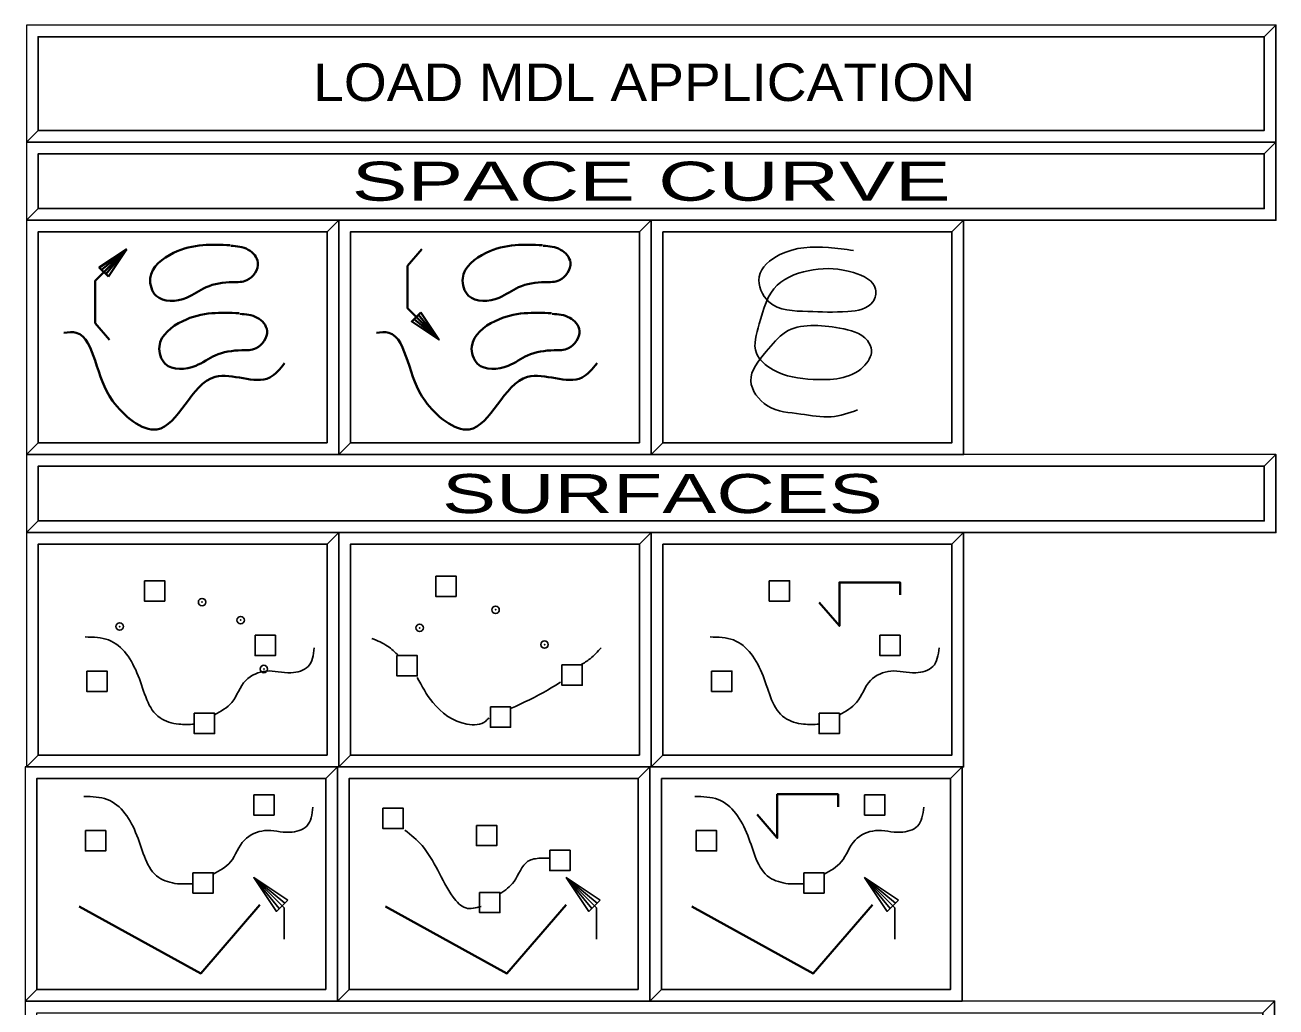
# Model space of a CAD drawing. Extents: x 95906.8 to 95923.6, y 90964.8 to 90972.8.
# Drawn here: x 95914.531 to 95916.132, y 90968.551 to 90969.808 of the extents above; entities that cross this region are included whole.
import ezdxf
from ezdxf.enums import TextEntityAlignment as Align

# ---------------------------------------------------------------- set-up
doc = ezdxf.new("R2010")
doc.units = 0
doc.header["$LTSCALE"] = 0.019
doc.header["$PDMODE"] = 32
doc.header["$PDSIZE"] = 0.0095
for name, color, linetype, lineweight in [('11', 7, 'Continuous', 25), ('17', 7, 'Continuous', 25), ('2', 7, 'Continuous', 13), ('3', 7, 'Continuous', 25), ('6', 7, 'Continuous', 25), ('7', 7, 'Continuous', 35)]:
    doc.layers.add(name, color=color, linetype=linetype, lineweight=lineweight)

msp = doc.modelspace()

# ---------------------------------------------------------------- linework, layer by layer
at = {"layer": '11'}
for points in [[(95914.5473, 90969.6733), (95916.1173, 90969.6733), (95916.1173, 90969.7933), (95914.5473, 90969.7933)], [(95914.5473, 90969.2733), (95914.9173, 90969.2733), (95914.9173, 90969.5433), (95914.5473, 90969.5433)], [(95914.9473, 90969.2733), (95915.3173, 90969.2733), (95915.3173, 90969.5433), (95914.9473, 90969.5433)], [(95915.3473, 90969.2733), (95915.7173, 90969.2733), (95915.7173, 90969.5433), (95915.3473, 90969.5433)], [(95914.5473, 90968.8733), (95914.9173, 90968.8733), (95914.9173, 90969.1433), (95914.5473, 90969.1433)], [(95914.9473, 90968.8733), (95915.3173, 90968.8733), (95915.3173, 90969.1433), (95914.9473, 90969.1433)], [(95915.3473, 90968.8733), (95915.7173, 90968.8733), (95915.7173, 90969.1433), (95915.3473, 90969.1433)], [(95914.5456, 90968.5733), (95914.9156, 90968.5733), (95914.9156, 90968.8433), (95914.5456, 90968.8433)], [(95914.9456, 90968.5733), (95915.3156, 90968.5733), (95915.3156, 90968.8433), (95914.9456, 90968.8433)], [(95915.3456, 90968.5733), (95915.7156, 90968.5733), (95915.7156, 90968.8433), (95915.3456, 90968.8433)]]:
    msp.add_lwpolyline(points, close=True, dxfattribs=at)
at = {"layer": '17'}
for points in [[(95914.5473, 90969.5733), (95916.1173, 90969.5733), (95916.1173, 90969.6433), (95914.5473, 90969.6433)], [(95914.5473, 90969.1733), (95916.1173, 90969.1733), (95916.1173, 90969.2433), (95914.5473, 90969.2433)]]:
    msp.add_lwpolyline(points, close=True, dxfattribs=at)
at = {"layer": '2'}
for points in [[(95914.5323, 90969.8083), (95914.5323, 90969.6583), (95914.5473, 90969.6733), (95914.5473, 90969.7933), (95916.1173, 90969.7933), (95916.1323, 90969.8083)], [(95914.5323, 90969.6583), (95914.5323, 90969.5583), (95914.5473, 90969.5733), (95914.5473, 90969.6433), (95916.1173, 90969.6433), (95916.1323, 90969.6583)], [(95914.5323, 90969.5583), (95914.5323, 90969.2583), (95914.5473, 90969.2733), (95914.5473, 90969.5433), (95914.9173, 90969.5433), (95914.9323, 90969.5583)], [(95914.9323, 90969.5583), (95914.9323, 90969.2583), (95914.9473, 90969.2733), (95914.9473, 90969.5433), (95915.3173, 90969.5433), (95915.3323, 90969.5583)], [(95915.3323, 90969.5583), (95915.3323, 90969.2583), (95915.3473, 90969.2733), (95915.3473, 90969.5433), (95915.7173, 90969.5433), (95915.7323, 90969.5583)], [(95914.5323, 90969.2583), (95914.5323, 90969.1583), (95914.5473, 90969.1733), (95914.5473, 90969.2433), (95916.1173, 90969.2433), (95916.1323, 90969.2583)], [(95914.5323, 90969.1583), (95914.5323, 90968.8583), (95914.5473, 90968.8733), (95914.5473, 90969.1433), (95914.9173, 90969.1433), (95914.9323, 90969.1583)], [(95914.9323, 90969.1583), (95914.9323, 90968.8583), (95914.9473, 90968.8733), (95914.9473, 90969.1433), (95915.3173, 90969.1433), (95915.3323, 90969.1583)], [(95915.3323, 90969.1583), (95915.3323, 90968.8583), (95915.3473, 90968.8733), (95915.3473, 90969.1433), (95915.7173, 90969.1433), (95915.7323, 90969.1583)], [(95914.5306, 90968.8583), (95914.5306, 90968.5583), (95914.5456, 90968.5733), (95914.5456, 90968.8433), (95914.9156, 90968.8433), (95914.9306, 90968.8583)], [(95914.9306, 90968.8583), (95914.9306, 90968.5583), (95914.9456, 90968.5733), (95914.9456, 90968.8433), (95915.3156, 90968.8433), (95915.3306, 90968.8583)], [(95915.3306, 90968.8583), (95915.3306, 90968.5583), (95915.3456, 90968.5733), (95915.3456, 90968.8433), (95915.7156, 90968.8433), (95915.7306, 90968.8583)], [(95914.5306, 90968.5583), (95914.5306, 90968.4583), (95914.5456, 90968.4733), (95914.5456, 90968.5433), (95916.1156, 90968.5433), (95916.1306, 90968.5583)]]:
    msp.add_lwpolyline(points, close=True, dxfattribs=at)
at = {"layer": '3'}
for points in [[(95914.5323, 90969.6583), (95916.1323, 90969.6583), (95916.1323, 90969.8083), (95916.1173, 90969.7933), (95916.1173, 90969.6733), (95914.5473, 90969.6733)], [(95914.5323, 90969.5583), (95916.1323, 90969.5583), (95916.1323, 90969.6583), (95916.1173, 90969.6433), (95916.1173, 90969.5733), (95914.5473, 90969.5733)], [(95914.5323, 90969.2583), (95914.9323, 90969.2583), (95914.9323, 90969.5583), (95914.9173, 90969.5433), (95914.9173, 90969.2733), (95914.5473, 90969.2733)], [(95914.9323, 90969.2583), (95915.3323, 90969.2583), (95915.3323, 90969.5583), (95915.3173, 90969.5433), (95915.3173, 90969.2733), (95914.9473, 90969.2733)], [(95915.3323, 90969.2583), (95915.7323, 90969.2583), (95915.7323, 90969.5583), (95915.7173, 90969.5433), (95915.7173, 90969.2733), (95915.3473, 90969.2733)], [(95914.5323, 90969.1583), (95916.1323, 90969.1583), (95916.1323, 90969.2583), (95916.1173, 90969.2433), (95916.1173, 90969.1733), (95914.5473, 90969.1733)], [(95914.5323, 90968.8583), (95914.9323, 90968.8583), (95914.9323, 90969.1583), (95914.9173, 90969.1433), (95914.9173, 90968.8733), (95914.5473, 90968.8733)], [(95914.9323, 90968.8583), (95915.3323, 90968.8583), (95915.3323, 90969.1583), (95915.3173, 90969.1433), (95915.3173, 90968.8733), (95914.9473, 90968.8733)], [(95915.3323, 90968.8583), (95915.7323, 90968.8583), (95915.7323, 90969.1583), (95915.7173, 90969.1433), (95915.7173, 90968.8733), (95915.3473, 90968.8733)], [(95914.5306, 90968.5583), (95914.9306, 90968.5583), (95914.9306, 90968.8583), (95914.9156, 90968.8433), (95914.9156, 90968.5733), (95914.5456, 90968.5733)], [(95914.9306, 90968.5583), (95915.3306, 90968.5583), (95915.3306, 90968.8583), (95915.3156, 90968.8433), (95915.3156, 90968.5733), (95914.9456, 90968.5733)], [(95915.3306, 90968.5583), (95915.7306, 90968.5583), (95915.7306, 90968.8583), (95915.7156, 90968.8433), (95915.7156, 90968.5733), (95915.3456, 90968.5733)], [(95914.5306, 90968.4583), (95916.1306, 90968.4583), (95916.1306, 90968.5583), (95916.1156, 90968.5433), (95916.1156, 90968.4733), (95914.5456, 90968.4733)]]:
    msp.add_lwpolyline(points, close=True, dxfattribs=at)
at = {"layer": '6', "lineweight": 35}
for p, q in [((95914.6315, 90969.4919), (95914.6605, 90969.5209)), ((95914.6605, 90969.5209), (95914.6342, 90969.4892)), ((95915.0315, 90969.4345), (95915.0605, 90969.4055)), ((95915.0605, 90969.4055), (95915.0342, 90969.4372))]:
    msp.add_line(p, q, dxfattribs=at)
at = {"layer": '6'}
for p, q in [((95914.8597, 90968.6803), (95914.8235, 90968.7165)), ((95914.8235, 90968.7165), (95914.8631, 90968.6837)), ((95915.2597, 90968.6803), (95915.2235, 90968.7165)), ((95915.2235, 90968.7165), (95915.2631, 90968.6837)), ((95915.6418, 90968.6803), (95915.6056, 90968.7165)), ((95915.6056, 90968.7165), (95915.6452, 90968.6837))]:
    msp.add_line(p, q, dxfattribs=at)
at = {"layer": '6', "lineweight": 35}
for points in [[(95914.6386, 90969.4051), (95914.6203, 90969.4267), (95914.6203, 90969.4807), (95914.6605, 90969.5209)], [(95914.6373, 90969.4861), (95914.6257, 90969.4977), (95914.6605, 90969.5209)], [(95914.6373, 90969.4861), (95914.6605, 90969.5209), (95914.6287, 90969.4948)], [(95915.0386, 90969.5213), (95915.0203, 90969.4997), (95915.0203, 90969.4457), (95915.0605, 90969.4055)], [(95915.0373, 90969.4403), (95915.0257, 90969.4287), (95915.0605, 90969.4055)], [(95915.0373, 90969.4403), (95915.0605, 90969.4055), (95915.0287, 90969.4316)], [(95915.5474, 90969.0686), (95915.5733, 90969.0387), (95915.5733, 90969.0946), (95915.6511, 90969.0946), (95915.6511, 90969.0786)], [(95915.4679, 90968.7972), (95915.4938, 90968.7673), (95915.4938, 90968.8232), (95915.5716, 90968.8232), (95915.5716, 90968.8072)], [(95914.6, 90968.6796), (95914.7556, 90968.5938), (95914.8314, 90968.6816)], [(95914.992, 90968.6796), (95915.1476, 90968.5938), (95915.2234, 90968.6816)], [(95915.3842, 90968.6796), (95915.5398, 90968.5938), (95915.6156, 90968.6816)]]:
    msp.add_lwpolyline(points, dxfattribs=at)
at = {"layer": '6'}
for points in [[(95914.6835, 90969.0966), (95914.7095, 90969.0966), (95914.7095, 90969.0706), (95914.6835, 90969.0706)], [(95915.0565, 90969.1026), (95915.0825, 90969.1026), (95915.0825, 90969.0766), (95915.0565, 90969.0766)], [(95915.4835, 90969.0966), (95915.5095, 90969.0966), (95915.5095, 90969.0706), (95915.4835, 90969.0706)], [(95914.8251, 90969.0268), (95914.8511, 90969.0268), (95914.8511, 90969.0008), (95914.8251, 90969.0008)], [(95915.6251, 90969.0268), (95915.6511, 90969.0268), (95915.6511, 90969.0008), (95915.6251, 90969.0008)], [(95915.0067, 90969.0008), (95915.0327, 90969.0008), (95915.0327, 90968.9748), (95915.0067, 90968.9748)], [(95915.2181, 90968.9889), (95915.2441, 90968.9889), (95915.2441, 90968.9629), (95915.2181, 90968.9629)], [(95914.6096, 90968.9809), (95914.6356, 90968.9809), (95914.6356, 90968.9549), (95914.6096, 90968.9549)], [(95915.4096, 90968.9809), (95915.4356, 90968.9809), (95915.4356, 90968.9549), (95915.4096, 90968.9549)], [(95914.7473, 90968.927), (95914.7733, 90968.927), (95914.7733, 90968.901), (95914.7473, 90968.901)], [(95915.1264, 90968.935), (95915.1524, 90968.935), (95915.1524, 90968.909), (95915.1264, 90968.909)], [(95915.5473, 90968.927), (95915.5733, 90968.927), (95915.5733, 90968.901), (95915.5473, 90968.901)], [(95914.8234, 90968.8225), (95914.8494, 90968.8225), (95914.8494, 90968.7965), (95914.8234, 90968.7965)], [(95915.6055, 90968.8225), (95915.6315, 90968.8225), (95915.6315, 90968.7965), (95915.6055, 90968.7965)], [(95914.9889, 90968.8053), (95915.0149, 90968.8053), (95915.0149, 90968.7793), (95914.9889, 90968.7793)], [(95914.6079, 90968.7766), (95914.6339, 90968.7766), (95914.6339, 90968.7506), (95914.6079, 90968.7506)], [(95915.1086, 90968.7834), (95915.1346, 90968.7834), (95915.1346, 90968.7574), (95915.1086, 90968.7574)], [(95915.39, 90968.7766), (95915.416, 90968.7766), (95915.416, 90968.7506), (95915.39, 90968.7506)], [(95915.2024, 90968.7515), (95915.2284, 90968.7515), (95915.2284, 90968.7255), (95915.2024, 90968.7255)], [(95914.7456, 90968.7227), (95914.7716, 90968.7227), (95914.7716, 90968.6967), (95914.7456, 90968.6967)], [(95915.5277, 90968.7227), (95915.5537, 90968.7227), (95915.5537, 90968.6967), (95915.5277, 90968.6967)], [(95915.1126, 90968.6976), (95915.1386, 90968.6976), (95915.1386, 90968.6716), (95915.1126, 90968.6716)]]:
    msp.add_lwpolyline(points, close=True, dxfattribs=at)
for points in [[(95914.8624, 90968.6377), (95914.8624, 90968.6776), (95914.8235, 90968.7165)], [(95914.8669, 90968.6875), (95914.8525, 90968.6731), (95914.8235, 90968.7165)], [(95914.8669, 90968.6875), (95914.8235, 90968.7165), (95914.8562, 90968.6768)], [(95915.2624, 90968.6377), (95915.2624, 90968.6776), (95915.2235, 90968.7165)], [(95915.2669, 90968.6875), (95915.2525, 90968.6731), (95915.2235, 90968.7165)], [(95915.2669, 90968.6875), (95915.2235, 90968.7165), (95915.2562, 90968.6768)], [(95915.6445, 90968.6377), (95915.6445, 90968.6776), (95915.6056, 90968.7165)], [(95915.649, 90968.6875), (95915.6346, 90968.6731), (95915.6056, 90968.7165)], [(95915.649, 90968.6875), (95915.6056, 90968.7165), (95915.6383, 90968.6768)]]:
    msp.add_lwpolyline(points, dxfattribs=at)
at = {"layer": '6', "lineweight": 35}
for points in [[(95914.7932, 90969.5264), (95914.7583, 90969.5264), (95914.7209, 90969.5164), (95914.691, 90969.484), (95914.6985, 90969.4616), (95914.7375, 90969.4591), (95914.7624, 90969.4724), (95914.7965, 90969.479), (95914.8148, 90969.4815), (95914.8289, 90969.504), (95914.8164, 90969.5206), (95914.794, 90969.5256)], [(95915.1932, 90969.5264), (95915.1583, 90969.5264), (95915.1209, 90969.5164), (95915.091, 90969.484), (95915.0985, 90969.4616), (95915.1375, 90969.4591), (95915.1624, 90969.4724), (95915.1965, 90969.479), (95915.2148, 90969.4815), (95915.2289, 90969.504), (95915.2164, 90969.5206), (95915.194, 90969.5256)], [(95914.8048, 90969.4392), (95914.7699, 90969.4392), (95914.7325, 90969.4292), (95914.7026, 90969.3968), (95914.7101, 90969.3744), (95914.7491, 90969.3719), (95914.774, 90969.3852), (95914.8081, 90969.3918), (95914.8264, 90969.3943), (95914.8405, 90969.4168), (95914.828, 90969.4334), (95914.8056, 90969.4384)], [(95915.2048, 90969.4392), (95915.1699, 90969.4392), (95915.1325, 90969.4292), (95915.1026, 90969.3968), (95915.1101, 90969.3744), (95915.1491, 90969.3719), (95915.174, 90969.3852), (95915.2081, 90969.3918), (95915.2264, 90969.3943), (95915.2405, 90969.4168), (95915.228, 90969.4334), (95915.2056, 90969.4384)], [(95914.5805, 90969.4142), (95914.5963, 90969.4142), (95914.6203, 90969.3785), (95914.6428, 90969.327), (95914.6993, 90969.2904), (95914.7741, 90969.3577), (95914.8439, 90969.3569), (95914.863, 90969.3752)], [(95914.9805, 90969.4142), (95914.9963, 90969.4142), (95915.0203, 90969.3785), (95915.0428, 90969.327), (95915.0993, 90969.2904), (95915.1741, 90969.3577), (95915.2439, 90969.3569), (95915.263, 90969.3752)]]:
    msp.add_spline(points, degree=3, dxfattribs=at)
at = {"layer": '6'}
for points in [[(95915.5913, 90969.5196), (95915.5594, 90969.5232), (95915.4972, 90969.5143), (95915.4706, 90969.4859), (95915.483, 90969.4539), (95915.5327, 90969.4415), (95915.5842, 90969.4415), (95915.6162, 90969.4539), (95915.6197, 90969.4699), (95915.5913, 90969.4912), (95915.5398, 90969.4948), (95915.4937, 90969.4752), (95915.4706, 90969.4255), (95915.467, 90969.3882), (95915.4883, 90969.3669), (95915.5398, 90969.3545), (95915.6038, 90969.3705), (95915.6144, 90969.3918), (95915.6091, 90969.4042), (95915.5736, 90969.4202), (95915.5043, 90969.4149), (95915.4795, 90969.39), (95915.4599, 90969.3527), (95915.4812, 90969.3208), (95915.5239, 90969.3101), (95915.5629, 90969.3066), (95915.5967, 90969.3154)], [(95914.6077, 90969.0247), (95914.6376, 90969.0208), (95914.6755, 90968.9749), (95914.7035, 90968.921), (95914.7274, 90968.913), (95914.7474, 90968.913)], [(95914.9748, 90969.0227), (95914.9948, 90969.0128), (95915.0087, 90969.0008)], [(95915.4077, 90969.0247), (95915.4376, 90969.0208), (95915.4755, 90968.9749), (95915.5035, 90968.921), (95915.5274, 90968.913), (95915.5474, 90968.913)], [(95914.7733, 90968.925), (95914.7953, 90968.9409), (95914.8132, 90968.9689), (95914.8391, 90968.9809), (95914.8711, 90968.9789), (95914.893, 90968.9868), (95914.901, 90969.0108)], [(95915.2422, 90968.9888), (95915.2541, 90968.9968), (95915.2681, 90969.0108)], [(95915.5733, 90968.925), (95915.5953, 90968.9409), (95915.6132, 90968.9689), (95915.6391, 90968.9809), (95915.6711, 90968.9789), (95915.693, 90968.9868), (95915.701, 90969.0108)], [(95915.0327, 90968.9729), (95915.0526, 90968.9409), (95915.0965, 90968.913), (95915.1205, 90968.917), (95915.1244, 90968.921)], [(95915.1524, 90968.933), (95915.2003, 90968.9569), (95915.2162, 90968.9669)], [(95914.606, 90968.8204), (95914.6359, 90968.8165), (95914.6738, 90968.7706), (95914.7018, 90968.7167), (95914.7257, 90968.7087), (95914.7457, 90968.7087)], [(95915.3881, 90968.8204), (95915.418, 90968.8165), (95915.4559, 90968.7706), (95915.4839, 90968.7167), (95915.5078, 90968.7087), (95915.5278, 90968.7087)], [(95914.7716, 90968.7207), (95914.7936, 90968.7366), (95914.8115, 90968.7646), (95914.8374, 90968.7766), (95914.8694, 90968.7746), (95914.8913, 90968.7825), (95914.8993, 90968.8065)], [(95915.5537, 90968.7207), (95915.5757, 90968.7366), (95915.5936, 90968.7646), (95915.6195, 90968.7766), (95915.6515, 90968.7746), (95915.6734, 90968.7825), (95915.6814, 90968.8065)], [(95915.017, 90968.7773), (95915.0389, 90968.7574), (95915.0789, 90968.6916), (95915.0948, 90968.6776), (95915.1148, 90968.6796)], [(95915.1387, 90968.6955), (95915.1567, 90968.7115), (95915.1746, 90968.7374), (95915.1906, 90968.7414), (95915.2025, 90968.7414)]]:
    msp.add_spline(points, degree=3, dxfattribs=at)
for p in [(95914.7573, 90969.0693), (95915.1331, 90969.0594), (95914.8067, 90969.0462), (95914.6518, 90969.038), (95915.0359, 90969.0363), (95915.1958, 90969.0149), (95914.8364, 90968.9836)]:
    msp.add_point(p, dxfattribs=at)

# ---------------------------------------------------------------- texts
at = {"layer": '6', "width": 1.1}
msp.add_text('LOAD MDL APPLICATION', height=0.048, dxfattribs=at).set_placement((95915.3233, 90969.711), align=Align.CENTER)
at = {"layer": '7'}
for s, width, p in [('      SPACE CURVE      ', 1.6, (95915.3323, 90969.5833)), ('        SURFACES       ', 1.55, (95915.3323, 90969.1833))]:
    msp.add_text(s, height=0.04999, dxfattribs=dict(at, width=width)).set_placement(p, align=Align.CENTER)

doc.saveas('drawing.dxf')
